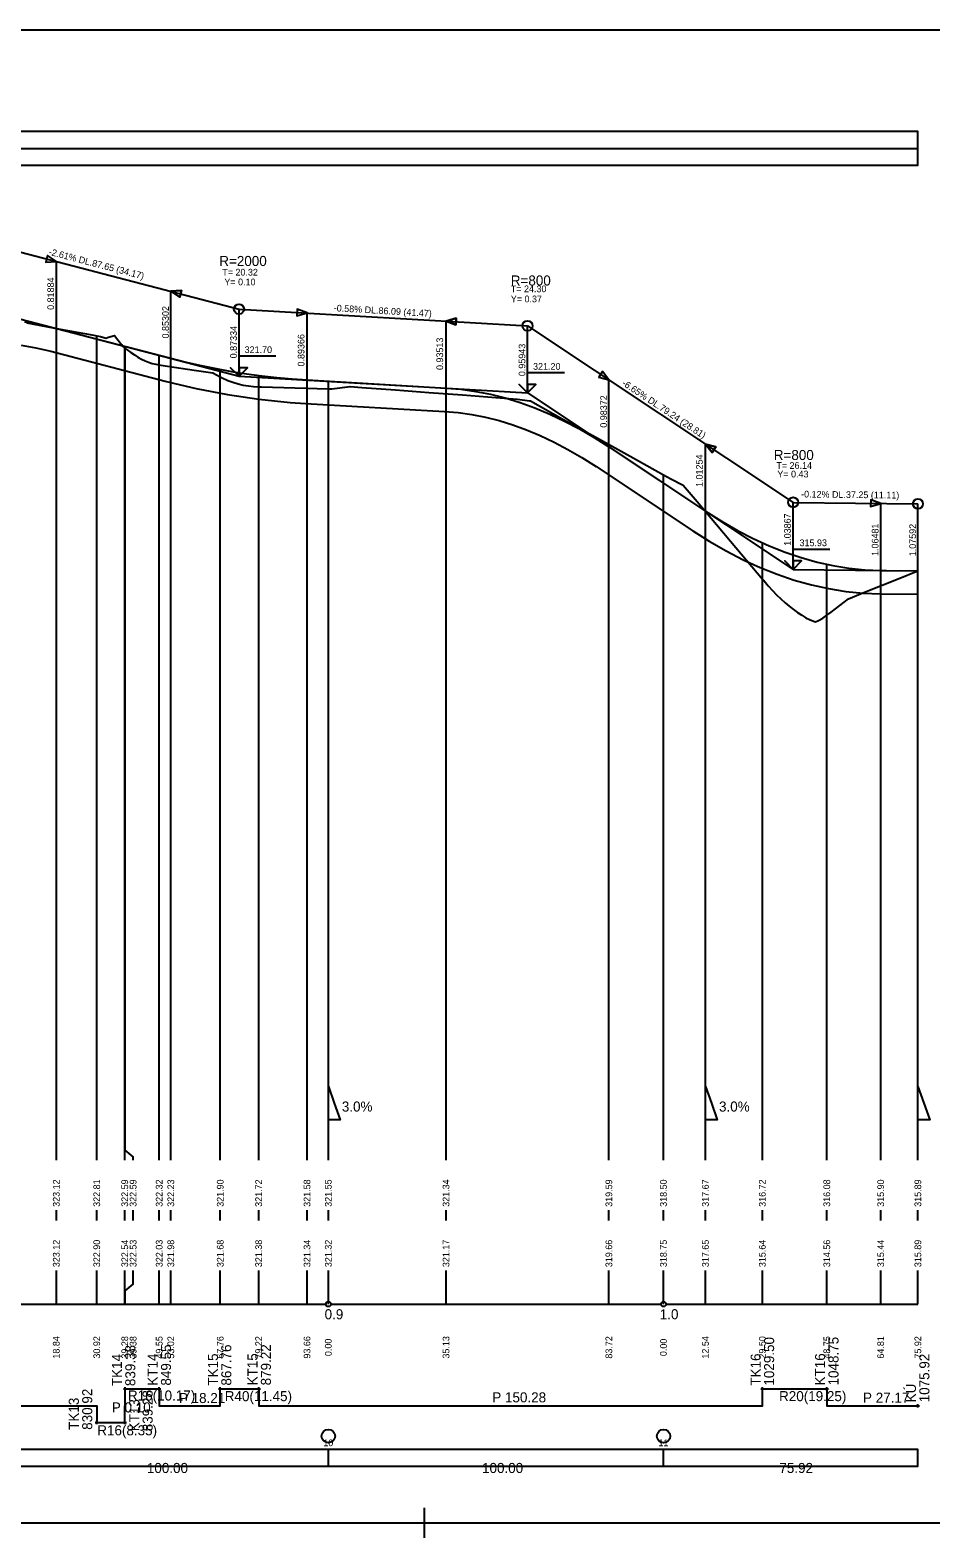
# Model space of a CAD drawing. Extents: x 1290 to 1438, y 129 to 174.
# Drawn here: x 1383.52 to 1410.39, y 128.92 to 173.92 of the extents above; entities that cross this region are included whole.
import ezdxf

# ---------------------------------------------------------------- set-up
doc = ezdxf.new("R2010")
doc.units = 0
for name, color, linetype in [('_drenaz', 7, 'Continuous'), ('KOTA', 7, 'Continuous'), ('NOVY_STAV', 7, 'Continuous'), ('NS_OBLOUK', 7, 'Continuous'), ('REZY_PO', 7, 'Continuous'), ('SESTAVY_REZU_PO', 7, 'Continuous'), ('SKLONOVE_POMERY', 7, 'Continuous'), ('SMEROVE_POMERY', 7, 'Continuous'), ('SMEROVE_POMERY_KOD', 7, 'Continuous'), ('SVK_STAT', 7, 'Continuous'), ('TABULKY', 7, 'Continuous'), ('u_pricne_rezy', 7, 'Continuous'), ('x_formát_rám', 7, 'Continuous')]:
    doc.layers.add(name, color=color, linetype=linetype)

msp = doc.modelspace()

# ---------------------------------------------------------------- linework, layer by layer
at = {"layer": '_drenaz'}
msp.add_lwpolyline([(1383.255, 164.514), (1383.689, 164.44), (1384.134, 164.337), (1387.546, 163.446), (1388.008, 163.331), (1388.474, 163.225), (1388.941, 163.129), (1389.407, 163.044), (1389.874, 162.97), (1390.341, 162.906), (1390.808, 162.853), (1391.275, 162.81), (1391.739, 162.778), (1395.88, 162.539), (1396.293, 162.503), (1396.698, 162.447), (1397.103, 162.367), (1397.509, 162.265), (1397.917, 162.14), (1398.327, 161.992), (1398.738, 161.821), (1399.151, 161.626), (1399.566, 161.407), (1399.983, 161.164), (1400.407, 160.894), (1403.289, 158.977), (1403.783, 158.663), (1404.285, 158.374), (1404.79, 158.113), (1405.296, 157.882), (1405.805, 157.679), (1406.315, 157.506), (1406.828, 157.363), (1407.341, 157.251), (1407.857, 157.168), (1408.373, 157.116), (1408.879, 157.095), (1410.001, 157.082)], dxfattribs=at)
at = {"layer": 'KOTA'}
for points in [[(1389.751, 163.594), (1389.501, 163.844), (1389.751, 163.594), (1389.751, 164.194), (1390.851, 164.194)], [(1389.751, 163.844), (1389.751, 163.594), (1390.001, 163.844), (1389.751, 163.844)], [(1389.751, 163.594), (1390.001, 163.844), (1389.751, 163.844)], [(1389.751, 163.594), (1389.751, 163.594)], [(1398.36, 163.097), (1398.11, 163.347), (1398.36, 163.097), (1398.36, 163.697), (1399.46, 163.697)], [(1398.36, 163.347), (1398.36, 163.097), (1398.61, 163.347), (1398.36, 163.347)], [(1398.36, 163.097), (1398.61, 163.347), (1398.36, 163.347)], [(1398.36, 163.097), (1398.36, 163.097)], [(1406.284, 157.825), (1406.034, 158.075), (1406.284, 157.825), (1406.284, 158.425), (1407.384, 158.425)], [(1406.284, 158.075), (1406.284, 157.825), (1406.534, 158.075), (1406.284, 158.075)], [(1406.284, 157.825), (1406.534, 158.075), (1406.284, 158.075)], [(1406.284, 157.825), (1406.284, 157.825)]]:
    msp.add_lwpolyline(points, dxfattribs=at)
at = {"layer": 'NOVY_STAV'}
for points in [[(1380.986, 167.882), (1389.751, 165.594)], [(1352.417, 148.331), (1357.497, 152.896), (1364.77, 152.953), (1371.787, 160.658), (1380.986, 165.882), (1389.751, 163.594), (1398.36, 163.097), (1406.284, 157.825), (1410.009, 157.782)], [(1383.354, 165.208), (1383.828, 165.126), (1384.301, 165.016), (1387.719, 164.124), (1388.17, 164.012), (1388.622, 163.909), (1389.074, 163.817), (1389.525, 163.735), (1389.977, 163.663), (1390.428, 163.601), (1390.88, 163.549), (1391.332, 163.508), (1391.783, 163.477), (1395.93, 163.237), (1396.372, 163.199), (1396.814, 163.137), (1397.255, 163.051), (1397.697, 162.94), (1398.139, 162.805), (1398.581, 162.645), (1399.022, 162.461), (1399.464, 162.252), (1399.906, 162.019), (1400.348, 161.762), (1400.789, 161.481), (1403.671, 159.564), (1404.146, 159.262), (1404.621, 158.988), (1405.096, 158.743), (1405.571, 158.525), (1406.047, 158.336), (1406.522, 158.176), (1406.997, 158.043), (1407.472, 157.939), (1407.947, 157.862), (1408.422, 157.814), (1408.898, 157.795), (1410.009, 157.782)], [(1389.751, 163.594), (1389.751, 165.594)], [(1389.751, 165.594), (1398.36, 165.097)], [(1398.36, 163.097), (1398.36, 165.097)], [(1398.36, 165.097), (1406.284, 159.825)], [(1406.284, 157.825), (1406.284, 159.825)], [(1406.284, 159.825), (1410.009, 159.782)], [(1410.009, 157.782), (1410.009, 159.782)]]:
    msp.add_lwpolyline(points, dxfattribs=at)
for centre in [(1389.751, 165.594), (1398.36, 165.097), (1406.284, 159.825), (1410.009, 159.782)]:
    msp.add_circle(centre, 0.15, dxfattribs=at)
at = {"layer": 'NS_OBLOUK'}
for points in [[(1383.986, 166.995), (1384.301, 167.016), (1384.036, 167.189), (1383.986, 166.995)], [(1384.301, 165.016), (1384.301, 167.016)], [(1387.719, 166.124), (1387.984, 165.952), (1388.034, 166.145), (1387.719, 166.124)], [(1387.719, 164.124), (1387.719, 166.124)], [(1391.478, 165.394), (1391.783, 165.477), (1391.489, 165.594), (1391.478, 165.394)], [(1391.783, 163.477), (1391.783, 165.477)], [(1395.93, 165.237), (1396.224, 165.12), (1396.235, 165.32), (1395.93, 165.237)], [(1395.93, 163.237), (1395.93, 165.237)], [(1400.484, 163.563), (1400.789, 163.481), (1400.595, 163.73), (1400.484, 163.563)], [(1400.789, 161.481), (1400.789, 163.481)], [(1403.671, 159.564), (1403.671, 161.564)], [(1403.671, 161.564), (1403.865, 161.315), (1403.976, 161.481), (1403.671, 161.564)], [(1408.597, 159.698), (1408.898, 159.795), (1408.599, 159.898), (1408.597, 159.698)], [(1408.898, 157.795), (1408.898, 159.795)]]:
    msp.add_lwpolyline(points, dxfattribs=at)
for points in [[(1384.301, 167.016), (1384.036, 167.189), (1383.986, 166.995)], [(1387.719, 166.124), (1388.034, 166.145), (1387.984, 165.952)], [(1391.783, 165.477), (1391.489, 165.594), (1391.478, 165.394)], [(1395.93, 165.237), (1396.235, 165.32), (1396.224, 165.12)], [(1400.789, 163.481), (1400.595, 163.73), (1400.484, 163.563)], [(1403.671, 161.564), (1403.976, 161.481), (1403.865, 161.315)], [(1408.898, 159.795), (1408.599, 159.898), (1408.597, 159.698)]]:
    msp.add_lwpolyline(points, close=True, dxfattribs=at)
at = {"layer": 'REZY_PO'}
msp.add_lwpolyline([(1383.417, 165.178), (1384.417, 164.995), (1385.417, 164.813), (1385.509, 164.796), (1385.614, 164.774), (1385.718, 164.747), (1385.778, 164.727), (1385.823, 164.746), (1385.927, 164.779), (1386.031, 164.801), (1386.036, 164.801), (1386.136, 164.679), (1386.24, 164.536), (1386.276, 164.482), (1386.345, 164.429), (1386.345, 164.429), (1386.345, 164.429), (1386.355, 164.421), (1386.386, 164.397), (1386.417, 164.373), (1386.523, 164.295), (1386.629, 164.223), (1386.735, 164.159), (1386.841, 164.101), (1386.947, 164.051), (1387.054, 164.008), (1387.16, 163.973), (1387.266, 163.945), (1387.372, 163.926), (1387.417, 163.92), (1388.417, 163.774), (1388.974, 163.693), (1389.193, 163.573), (1389.305, 163.513), (1389.356, 163.489), (1389.417, 163.464), (1389.57, 163.409), (1389.724, 163.363), (1389.878, 163.327), (1390.031, 163.3), (1390.185, 163.281), (1390.338, 163.273), (1390.417, 163.271), (1391.417, 163.242), (1392.417, 163.214), (1392.521, 163.211), (1393.065, 163.282), (1393.417, 163.255), (1394.417, 163.18), (1395.417, 163.105), (1396.417, 163.029), (1397.417, 162.954), (1398.062, 162.905), (1398.417, 162.855), (1398.444, 162.851), (1399.417, 162.312), (1400.417, 161.757), (1401.417, 161.203), (1402.417, 160.648), (1402.635, 160.527), (1402.999, 160.342), (1403.417, 159.847), (1404.417, 158.662), (1405.367, 157.537), (1405.367, 157.537), (1405.367, 157.537), (1405.392, 157.507), (1405.417, 157.478), (1405.542, 157.334), (1405.667, 157.198), (1405.792, 157.067), (1405.917, 156.945), (1406.042, 156.829), (1406.167, 156.722), (1406.292, 156.623), (1406.417, 156.534), (1406.542, 156.453), (1406.667, 156.383), (1406.792, 156.322), (1406.917, 156.271), (1406.95, 156.26), (1406.953, 156.255), (1407.042, 156.294), (1407.167, 156.366), (1407.292, 156.455), (1407.292, 156.455), (1407.292, 156.455), (1407.417, 156.551), (1407.933, 156.949), (1408.417, 157.143), (1409.417, 157.544), (1410.009, 157.782), (1410.009, 157.782)], dxfattribs=at)
at = {"layer": 'SESTAVY_REZU_PO'}
for points in [[(1382.492, 135.894), (1392.342, 135.894)], [(1392.492, 135.894), (1402.342, 135.894)], [(1402.492, 135.894), (1410.009, 135.894)]]:
    msp.add_lwpolyline(points, dxfattribs=at)
for centre in [(1392.417, 135.894), (1402.417, 135.894)]:
    msp.add_circle(centre, 0.075, dxfattribs=at)
at = {"layer": 'SKLONOVE_POMERY'}
for points in [[(1392.417, 141.394), (1392.417, 142.394), (1392.417, 142.394), (1392.592, 141.894), (1392.767, 141.394), (1392.417, 141.394)], [(1403.671, 141.394), (1403.671, 142.394), (1403.671, 142.394), (1403.846, 141.894), (1404.021, 141.394), (1403.671, 141.394)], [(1410.009, 141.394), (1410.009, 142.394), (1410.009, 142.394), (1410.184, 141.894), (1410.359, 141.394), (1410.009, 141.394)]]:
    msp.add_lwpolyline(points, dxfattribs=at)
at = {"layer": 'SMEROVE_POMERY'}
msp.add_lwpolyline([(1376.832, 132.862), (1385.509, 132.862), (1385.509, 132.362), (1386.345, 132.362), (1386.345, 132.862), (1386.355, 132.862), (1386.355, 133.362), (1387.372, 133.362), (1387.372, 132.862), (1389.193, 132.862), (1389.193, 133.362), (1390.338, 133.362), (1390.338, 132.862), (1405.367, 132.862), (1405.367, 133.362), (1407.292, 133.362), (1407.292, 132.862), (1410.009, 132.862)], dxfattribs=at)
at = {"layer": 'SMEROVE_POMERY_KOD'}
for points in [[(1386.305, 133.362), (1386.405, 133.362)], [(1386.355, 133.312), (1386.355, 133.412)], [(1387.322, 133.362), (1387.422, 133.362)], [(1387.372, 133.312), (1387.372, 133.412)], [(1389.143, 133.362), (1389.243, 133.362)], [(1389.193, 133.312), (1389.193, 133.412)], [(1390.288, 133.362), (1390.388, 133.362)], [(1390.338, 133.312), (1390.338, 133.412)], [(1405.317, 133.362), (1405.417, 133.362)], [(1405.367, 133.312), (1405.367, 133.412)], [(1407.242, 133.362), (1407.342, 133.362)], [(1407.292, 133.312), (1407.292, 133.412)], [(1409.959, 132.862), (1410.059, 132.862)], [(1410.009, 132.812), (1410.009, 132.912)], [(1385.459, 132.362), (1385.559, 132.362)], [(1385.509, 132.312), (1385.509, 132.412)], [(1386.295, 132.362), (1386.395, 132.362)], [(1386.345, 132.312), (1386.345, 132.412)]]:
    msp.add_lwpolyline(points, dxfattribs=at)
at = {"layer": 'SVK_STAT'}
for points in [[(1384.301, 140.194), (1384.301, 165.016)], [(1385.509, 140.194), (1385.509, 164.796)], [(1386.345, 140.194), (1386.345, 164.483)], [(1386.595, 140.194), (1386.595, 140.294), (1386.355, 140.494), (1386.355, 164.48)], [(1387.372, 140.194), (1387.372, 164.215)], [(1387.719, 140.194), (1387.719, 164.124)], [(1389.193, 140.194), (1389.193, 163.795)], [(1390.338, 140.194), (1390.338, 163.613)], [(1391.783, 140.194), (1391.783, 163.477)], [(1392.417, 140.194), (1392.417, 163.44)], [(1395.93, 140.194), (1395.93, 163.237)], [(1400.789, 140.194), (1400.789, 161.551)], [(1402.417, 140.194), (1402.417, 160.648)], [(1403.671, 140.194), (1403.671, 159.564)], [(1405.367, 140.194), (1405.367, 158.619)], [(1407.292, 140.194), (1407.292, 157.978)], [(1408.898, 140.194), (1408.898, 157.795)], [(1410.009, 140.194), (1410.009, 157.782)], [(1384.301, 138.394), (1384.301, 138.694)], [(1385.509, 138.394), (1385.509, 138.694)], [(1386.345, 138.394), (1386.345, 138.694)], [(1386.595, 138.394), (1386.595, 138.694)], [(1387.372, 138.394), (1387.372, 138.694)], [(1387.719, 138.394), (1387.719, 138.694)], [(1389.193, 138.394), (1389.193, 138.694)], [(1390.338, 138.394), (1390.338, 138.694)], [(1391.783, 138.394), (1391.783, 138.694)], [(1392.417, 138.394), (1392.417, 138.694)], [(1395.93, 138.394), (1395.93, 138.694)], [(1400.789, 138.394), (1400.789, 138.694)], [(1402.417, 138.394), (1402.417, 138.694)], [(1403.671, 138.394), (1403.671, 138.694)], [(1405.367, 138.394), (1405.367, 138.694)], [(1407.292, 138.394), (1407.292, 138.694)], [(1408.898, 138.394), (1408.898, 138.694)], [(1410.009, 138.394), (1410.009, 138.694)], [(1384.301, 135.894), (1384.301, 136.894)], [(1385.509, 135.894), (1385.509, 136.894)], [(1386.345, 135.894), (1386.345, 136.894)], [(1386.355, 135.894), (1386.355, 136.294), (1386.595, 136.494), (1386.595, 136.894)], [(1387.372, 135.894), (1387.372, 136.894)], [(1387.719, 135.894), (1387.719, 136.894)], [(1389.193, 135.894), (1389.193, 136.894)], [(1390.338, 135.894), (1390.338, 136.894)], [(1391.783, 135.894), (1391.783, 136.894)], [(1392.417, 135.894), (1392.417, 136.894)], [(1395.93, 135.894), (1395.93, 136.894)], [(1400.789, 135.894), (1400.789, 136.894)], [(1402.417, 135.894), (1402.417, 136.894)], [(1403.671, 135.894), (1403.671, 136.894)], [(1405.367, 135.894), (1405.367, 136.894)], [(1407.292, 135.894), (1407.292, 136.894)], [(1408.898, 135.894), (1408.898, 136.894)], [(1410.009, 135.894), (1410.009, 136.894)]]:
    msp.add_lwpolyline(points, dxfattribs=at)
at = {"layer": 'TABULKY'}
for points in [[(1302.417, 169.89), (1410.009, 169.89), (1410.009, 170.89), (1302.417, 170.89), (1302.417, 169.89)], [(1302.417, 170.39), (1410.009, 170.39)]]:
    msp.add_lwpolyline(points, dxfattribs=at)
at = {"layer": 'u_pricne_rezy'}
for points in [[(1302.417, 131.054), (1410.009, 131.054), (1410.009, 131.554), (1302.417, 131.554), (1302.417, 131.054)], [(1392.417, 131.054), (1392.417, 131.554)], [(1402.417, 131.054), (1402.417, 131.554)]]:
    msp.add_lwpolyline(points, dxfattribs=at)
for centre in [(1392.417, 131.954), (1402.417, 131.954)]:
    msp.add_circle(centre, 0.2, dxfattribs=at)
at = {"layer": 'x_formát_rám'}
msp.add_line((1395.283, 128.918), (1395.283, 129.818), dxfattribs=at)
msp.add_lwpolyline([(1290.283, 129.368), (1437.283, 129.368), (1437.283, 173.918), (1290.283, 173.918)], close=True, dxfattribs=at)

# ---------------------------------------------------------------- texts
at = {"layer": 'KOTA'}
for s, p in [('321.70', (1389.918, 164.281)), ('321.20', (1398.524, 163.781)), ('315.93', (1406.475, 158.517))]:
    msp.add_text(s, height=0.2, dxfattribs=at).set_placement(p)
at = {"layer": 'NOVY_STAV'}
for s, rotation, p in [('-2.61% DL.87.65 (34.17)', 345.3722, (1384.057, 167.217)), ('-0.58% DL.86.09 (41.47)', 356.6933, (1392.573, 165.53)), (' 0.87334', 90, (1389.687, 164.049)), (' 0.95943', 90, (1398.295, 163.517)), ('-6.65% DL.79.24 (28.81)', 326.3691, (1401.158, 163.336)), ('-0.12% DL.37.25 (11.11)', 359.324, (1406.521, 159.972)), (' 1.03867', 90, (1406.215, 158.454)), (' 1.07592', 90, (1409.95, 158.142))]:
    msp.add_text(s, height=0.2, rotation=rotation, dxfattribs=at).set_placement(p)
at = {"layer": 'NS_OBLOUK'}
for s, height, p in [('R=2000', 0.3, (1389.162, 166.879)), ('T= 20.32', 0.2, (1389.251, 166.594)), ('Y= 0.10', 0.2, (1389.314, 166.304)), ('R=800', 0.3, (1397.86, 166.297)), ('T= 24.30', 0.2, (1397.86, 166.097)), ('Y= 0.37', 0.2, (1397.86, 165.797)), ('R=800', 0.3, (1405.707, 161.088)), ('T= 26.14', 0.2, (1405.784, 160.825)), ('Y= 0.43', 0.2, (1405.813, 160.569))]:
    msp.add_text(s, height=height, dxfattribs=at).set_placement(p)
for s, p in [(' 0.81884', (1384.232, 165.495)), (' 0.85302', (1387.658, 164.642)), (' 0.89366', (1391.704, 163.806)), (' 0.93513', (1395.841, 163.701)), (' 0.98372', (1400.73, 161.979)), (' 1.01254', (1403.586, 160.212)), (' 1.06481', (1408.831, 158.15))]:
    msp.add_text(s, height=0.2, rotation=90, dxfattribs=at).set_placement(p)
at = {"layer": 'SESTAVY_REZU_PO'}
for s, p in [('0.9', (1392.305, 135.442)), ('1.0', (1402.305, 135.442))]:
    msp.add_text(s, height=0.3, dxfattribs=at).set_placement(p)
at = {"layer": 'SKLONOVE_POMERY'}
for p in [(1392.819, 141.642), (1404.073, 141.642)]:
    msp.add_text('3.0%', height=0.3, dxfattribs=at).set_placement(p)
at = {"layer": 'SMEROVE_POMERY'}
for s, p in [('R16(10.17)', (1386.438, 133.017)), ('P 18.21', (1387.958, 132.942)), ('R40(11.45)', (1389.326, 132.998)), ('P 150.28', (1397.308, 132.962)), ('R20(19.25)', (1405.865, 132.998)), ('P 27.17', (1408.37, 132.952)), ('P 0.10', (1385.956, 132.662)), ('R16(8.35)', (1385.522, 131.978))]:
    msp.add_text(s, height=0.3, dxfattribs=at).set_placement(p)
at = {"layer": 'SMEROVE_POMERY_KOD'}
for s, p in [('839.38', (1386.657, 133.448)), ('849.55', (1387.722, 133.462)), ('867.76', (1389.522, 133.462)), ('879.22', (1390.703, 133.469)), ('1029.50', (1405.717, 133.462)), ('1048.75', (1407.638, 133.467)), ('TK14', (1386.257, 133.448)), ('KT14', (1387.322, 133.462)), ('TK15', (1389.122, 133.462)), ('KT15', (1390.303, 133.469)), ('TK16', (1405.317, 133.462)), ('KT16', (1407.238, 133.467)), ('1075.92', (1410.35, 132.964)), ('830.92', (1385.372, 132.143)), ('839.28', (1387.174, 132.1)), ('KÚ', (1409.95, 132.964)), ('TK13', (1384.972, 132.143)), ('KT13', (1386.774, 132.1))]:
    msp.add_text(s, height=0.3, rotation=90, dxfattribs=at).set_placement(p)
at = {"layer": 'SVK_STAT'}
for s, p in [(' 323.12', (1384.398, 138.724)), (' 322.81', (1385.606, 138.724)), (' 322.59', (1386.442, 138.724)), (' 322.59', (1386.692, 138.724)), (' 322.32', (1387.469, 138.724)), (' 322.23', (1387.816, 138.724)), (' 321.90', (1389.29, 138.724)), (' 321.72', (1390.435, 138.724)), (' 321.58', (1391.88, 138.724)), (' 321.55', (1392.514, 138.724)), (' 321.34', (1396.027, 138.724)), (' 319.59', (1400.886, 138.724)), (' 318.50', (1402.514, 138.724)), (' 317.67', (1403.768, 138.724)), (' 316.72', (1405.464, 138.724)), (' 316.08', (1407.389, 138.724)), (' 315.90', (1408.995, 138.724)), (' 315.89', (1410.106, 138.724)), (' 323.12', (1384.398, 136.924)), (' 322.90', (1385.606, 136.924)), (' 322.54', (1386.442, 136.924)), (' 322.53', (1386.692, 136.924)), (' 322.03', (1387.469, 136.924)), (' 321.98', (1387.816, 136.924)), (' 321.68', (1389.29, 136.924)), (' 321.38', (1390.435, 136.924)), (' 321.34', (1391.88, 136.924)), (' 321.32', (1392.514, 136.924)), (' 321.17', (1396.027, 136.924)), (' 319.66', (1400.886, 136.924)), (' 318.75', (1402.514, 136.924)), (' 317.65', (1403.768, 136.924)), (' 315.64', (1405.464, 136.924)), (' 314.56', (1407.389, 136.924)), (' 315.44', (1408.995, 136.924)), (' 315.89', (1410.106, 136.924)), (' 18.84', (1384.398, 134.194)), (' 30.92', (1385.606, 134.194)), (' 39.28', (1386.442, 134.194)), (' 39.38', (1386.692, 134.194)), (' 49.55', (1387.469, 134.194)), (' 53.02', (1387.816, 134.194)), (' 67.76', (1389.29, 134.194)), (' 79.22', (1390.435, 134.194)), (' 93.66', (1391.88, 134.194)), ('  0.00', (1392.514, 134.194)), (' 35.13', (1396.027, 134.194)), (' 83.72', (1400.886, 134.194)), ('  0.00', (1402.514, 134.194)), (' 12.54', (1403.768, 134.194)), (' 29.50', (1405.464, 134.194)), (' 48.75', (1407.389, 134.194)), (' 64.81', (1408.995, 134.194)), (' 75.92', (1410.106, 134.194))]:
    msp.add_text(s, height=0.2, rotation=90, dxfattribs=at).set_placement(p)
at = {"layer": 'u_pricne_rezy'}
for s, height, p in [('10', 0.2, (1392.266, 131.654)), ('11', 0.2, (1402.266, 131.654)), ('100.00', 0.3, (1387.002, 130.854)), ('100.00', 0.3, (1397.002, 130.854)), ('75.92', 0.3, (1405.873, 130.854))]:
    msp.add_text(s, height=height, dxfattribs=at).set_placement(p)

doc.saveas('drawing.dxf')
